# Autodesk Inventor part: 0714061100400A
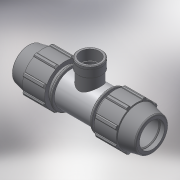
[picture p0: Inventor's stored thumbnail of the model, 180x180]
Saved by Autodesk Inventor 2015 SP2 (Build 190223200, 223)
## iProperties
Created: 2017-02
Part Number: 0714061100400A
Material: Generic
Description: PLASSON TEE WITH THREADED FEMALE OFFTAKE 110-4"-110
Document SubType Name: Modeling
Designer: KIM
Mass: 92.6774 g
Surface Area: 199.44 cm^2
Volume: 66.1981 cm^3
Density: 1 g/cm^3
Appearance: Default
Author: KIM
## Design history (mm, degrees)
derived "87140.ipt"
feature "Solid1::87140.ipt"
feature "Solid2::87140.ipt"
tag "TaggingFeature1"
body "Solid1"
other parameters: "d4" = 21.29167, "d5" = 61.32, "d7" = 181, "d11" = 8.51667, "d13" = 120 deg, "d14" = 143, "d15" = 10 deg, "d16" = 157.47, "d18" = 5.5, "d19" = 35 deg, "d20" = 17.5 deg, "d21" = 168.33, "d23" = 0, "d25" = 360 deg, "d27" = 3.62, "d33" = 2.2, "d42" = 91.98, "d43" = 5.43, "d46" = 3.3, "d68" = 15.33, "d76" = 110.072, "d80" = 3.30216, "d91" = 135.75, "d93" = 198, "d95" = 99, "d115" = 137.59, "d116" = 135 deg, "d117" = 126.5828, "d118" = 511, "d119" = 99, "d121" = 0, "d122" = 99, "d124" = 0, "d128" = 0, "d129" = 11, "d130" = 15, "d131" = 0.3, "d132" = 0.3, "d133" = 137.59, "E_" = 181, "l_" = 198, "Rp_" = 110.072, "H_" = 511
